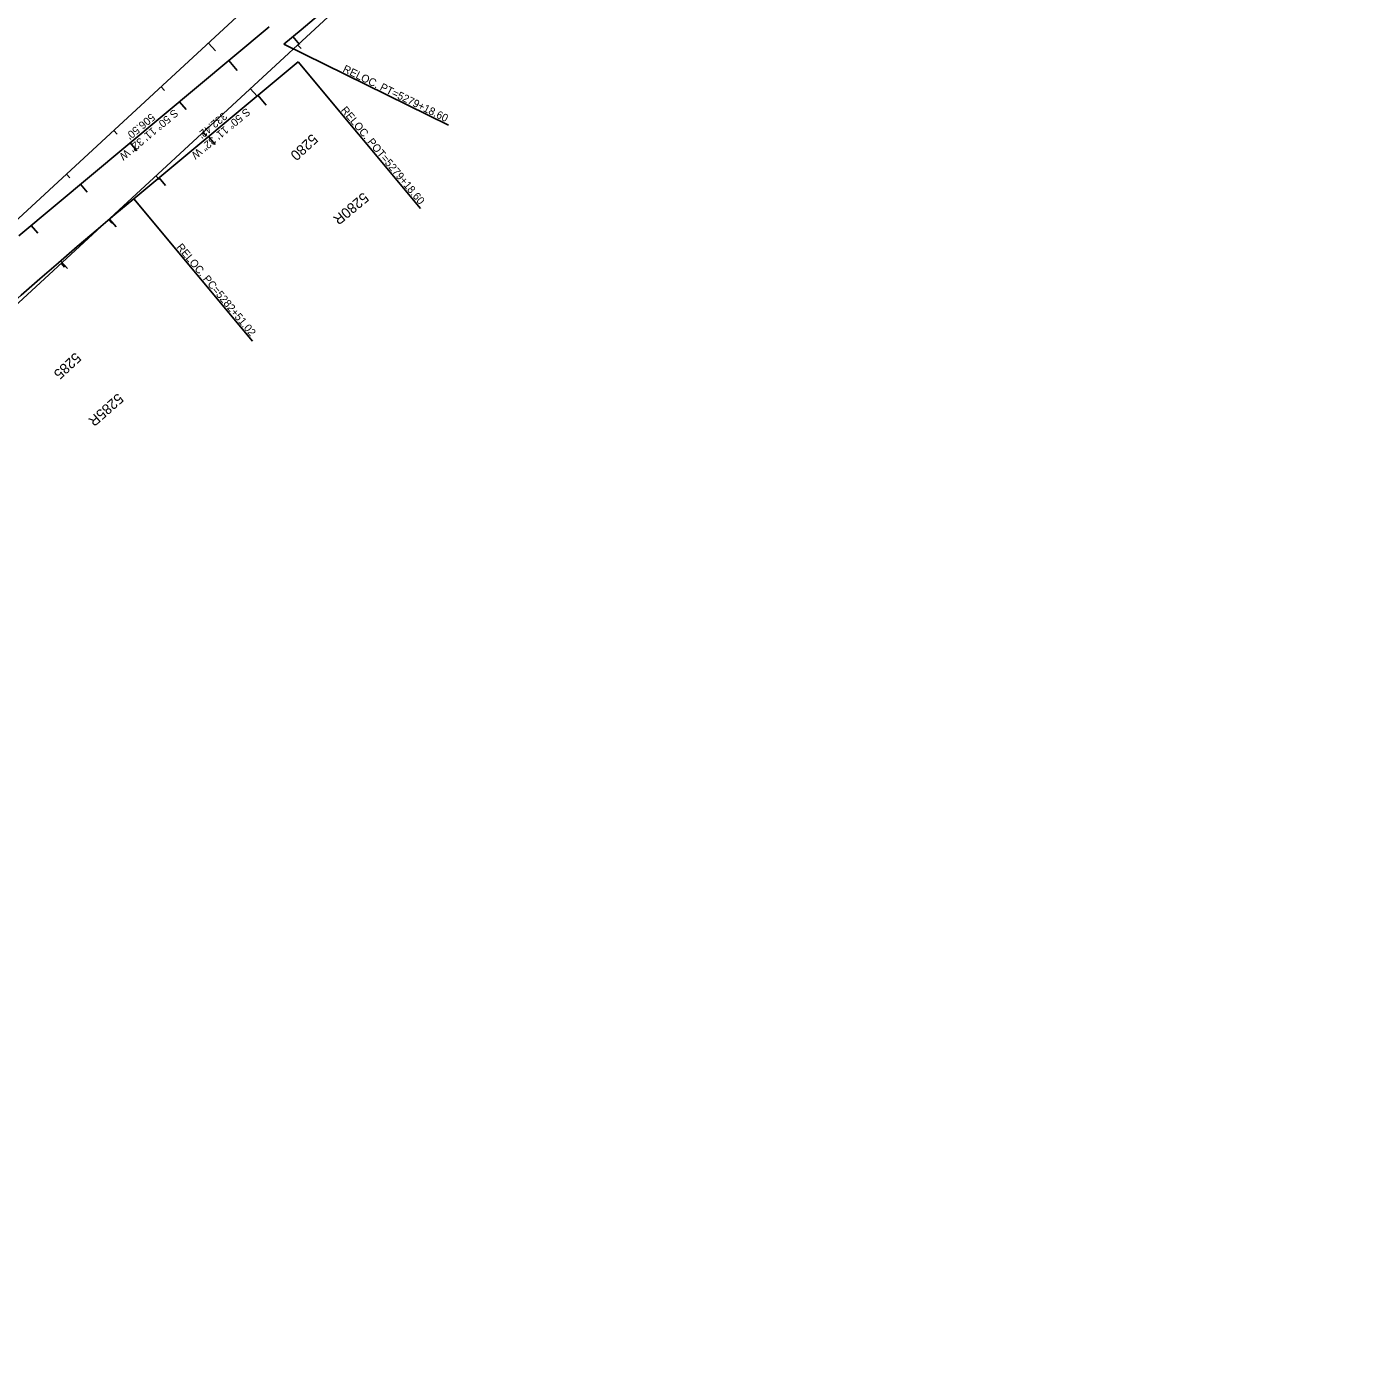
# Model space of a CAD drawing. Extents: x 2160877 to 2175861, y 601747 to 617724.
# Drawn here: x 2163959 to 2166050, y 604369 to 606444 of the extents above; entities that cross this region are included whole.
import ezdxf

# ---------------------------------------------------------------- set-up
doc = ezdxf.new("R2010")
doc.units = 0
for name, color, linetype in [('RD_HC_Cl', 7, 'Continuous'), ('RD_HC_CL_Rel', 7, 'Continuous'), ('RD_HC_Data_Rel', 7, 'Continuous'), ('RD_HC_Data_Tic', 7, 'Continuous'), ('RD_HC_Data_Tic_Rel', 7, 'Continuous'), ('RD_HC_TX_Rel_Sta50', 7, 'Continuous'), ('RD_HC_TX_Rel_StaOther', 7, 'Continuous'), ('RD_HC_TX_StaOther', 7, 'Continuous')]:
    doc.layers.add(name, color=color, linetype=linetype)

msp = doc.modelspace()

# ---------------------------------------------------------------- linework, layer by layer
at = {"layer": 'RD_HC_Cl'}
for p, q in [((2172207.3, 613775.1), (2163672.2, 605893.8)), ((2172272.5, 613704.6), (2163737.4, 605823.3))]:
    msp.add_line(p, q, dxfattribs=at)
at = {"layer": 'RD_HC_CL_Rel'}
for p, q in [((2164335.8, 606444.4), (2163946.7, 606120.1)), ((2164380.9, 606390.4), (2164125.5, 606177.5))]:
    msp.add_line(p, q, dxfattribs=at)
for centre, radius, start, end in [((2135996.9, 640448.5), 44300, 309.80773, 312.71947), ((2169810, 599356.6), 8879.1, 129.80773, 145.62858)]:
    msp.add_arc(centre, radius, start, end, dxfattribs=at)
at = {"layer": 'RD_HC_Data_Rel'}
for p, q in [((2164358.3, 606417.4), (2164614.3, 606291.9)), ((2164380.9, 606390.4), (2164570.9, 606162.4)), ((2164125.5, 606177.5), (2164309.7, 605956.5))]:
    msp.add_line(p, q, dxfattribs=at)
at = {"layer": 'RD_HC_Data_Tic'}
for p, q in [((2164241.3, 606419.3), (2164252.1, 606407.5)), ((2164379.9, 606416.6), (2164385.3, 606410.7)), ((2164167.8, 606351.4), (2164173.3, 606345.6)), ((2164306.4, 606348.8), (2164317.3, 606337)), ((2164094.4, 606283.6), (2164099.8, 606277.7)), ((2164233, 606280.9), (2164238.4, 606275)), ((2164020.9, 606215.8), (2164026.3, 606209.9)), ((2164159.5, 606213.1), (2164164.9, 606207.2)), ((2164086, 606145.2), (2164091.4, 606139.4)), ((2164012.5, 606077.4), (2164018, 606071.5))]:
    msp.add_line(p, q, dxfattribs=at)
at = {"layer": 'RD_HC_Data_Tic_Rel'}
for p, q in [((2164372.6, 606429.3), (2164382.9, 606417)), ((2164273.3, 606392.3), (2164286.1, 606376.9)), ((2164196.5, 606328.3), (2164206.7, 606316)), ((2164318.3, 606338.2), (2164331.1, 606322.9)), ((2164119.7, 606264.2), (2164129.9, 606251.9)), ((2164241.5, 606274.2), (2164251.7, 606261.9)), ((2164164.7, 606210.2), (2164174.9, 606197.9)), ((2164042.8, 606200.2), (2164053.1, 606187.9)), ((2164087.9, 606146.1), (2164098.3, 606133.8)), ((2163966, 606136.2), (2163976.3, 606123.9)), ((2164011.8, 606081.2), (2164022.3, 606069.1))]:
    msp.add_line(p, q, dxfattribs=at)

# ---------------------------------------------------------------- texts
at = {"layer": 'RD_HC_Data_Rel'}
for s, rotation, p in [('RELOC. PT=5279+18.60', 333.8917, (2164449, 606375.2)), ('RELOC. POT=5279+18.60', 309.8077, (2164446.4, 606314.8)), ('RELOC. PC=5282+51.02', 309.8077, (2164191, 606102))]:
    msp.add_text(s, height=12, rotation=rotation, dxfattribs=at).set_placement(p)
at = {"layer": 'RD_HC_TX_Rel_Sta50'}
for s, rotation, p in [('5280R', 219.8077, (2164482, 606188.3)), ('5285R', 221.4144, (2164100.7, 605876.4))]:
    msp.add_text(s, height=16, rotation=rotation, dxfattribs=at).set_placement(p)
at = {"layer": 'RD_HC_TX_Rel_StaOther'}
for s, p in [('S 50%%d 11\' 32" W', (2164188.2, 606317.5)), ("506.50'", (2164152.3, 606311)), ('S 50%%d 11\' 32" W', (2164300.1, 606319.2)), ("332.42'", (2164264.2, 606312.7))]:
    msp.add_text(s, height=12, rotation=219.8077, dxfattribs=at).set_placement(p)
at = {"layer": 'RD_HC_TX_StaOther'}
for s, p in [('5280', (2164402.3, 606279.4)), ('5285', (2164034.6, 605939.8))]:
    msp.add_text(s, height=16, rotation=222.7195, dxfattribs=at).set_placement(p)

doc.saveas('drawing.dxf')
